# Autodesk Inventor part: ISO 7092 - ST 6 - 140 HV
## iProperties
Created: 2007-03
Part Number: ISO 7092 - ST 6 - 140 HV
Material: Stainless Steel
Description: Plain washers-Small series-Product grade A
Document SubType Name: Modeling
Standard: ISO 7092
Designer: Admin
Standard Revision: Second edition 2000-06-01
Standards Organization: ISO
Language: en-US
Size Designation: ST 6 - 140 HV
Categories: <MemberInstance><Categories><Category DisplayName="Fasteners" InternalName="e4da775c-781d-43d5-af7c-5136215cf5a6" Mnemonic="FSTN"><Category DisplayName="Washers
Density: 1 g/cm^3
IsCustomPart: 0
Author: Admin
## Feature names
1. Body [Extrusion]
